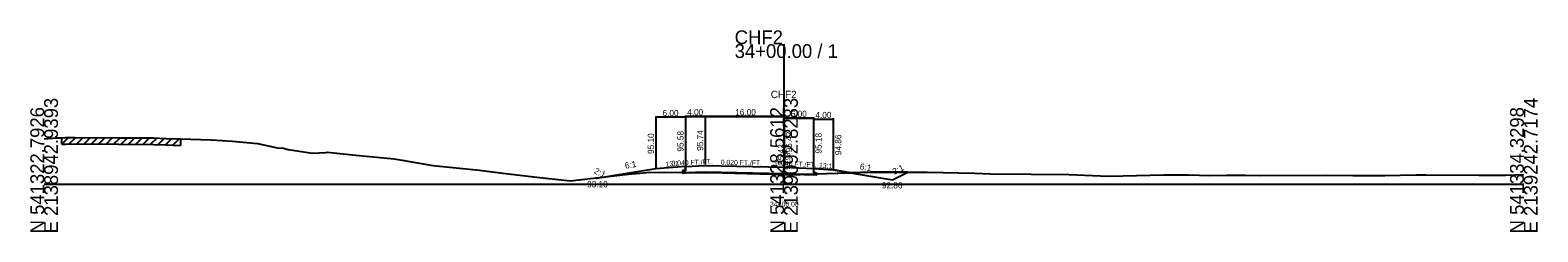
# Model space of a CAD drawing. Extents: x -12831 to 2303, y -10 to 39065.
# Drawn here: x 997.2 to 1302.8, y 7990.3 to 8031.2 of the extents above; entities that cross this region are included whole.
import ezdxf

# ---------------------------------------------------------------- set-up
doc = ezdxf.new("R2010")
doc.units = 0
for name, color, linetype in [('Level 5', 7, 'Continuous'), ('Level 53', 7, 'Continuous'), ('Level 54', 7, 'Continuous'), ('Level 55', 7, 'Continuous'), ('Level 7', 7, 'Continuous'), ('RD_GPK_XS_Cell', 7, 'Continuous'), ('RD_XS_EwShp', 7, 'Continuous'), ('RD_XS_ExGround', 7, 'Continuous'), ('RD_XS_ExPaveRet', 7, 'Continuous'), ('RD_XS_Pave', 7, 'Continuous'), ('RD_XS_TX_Baseline', 7, 'Continuous'), ('RD_XS_TX_Ditch', 7, 'Continuous'), ('RD_XS_TX_Elev_EX', 7, 'Continuous'), ('RD_XS_TX_Elev_PR', 7, 'Continuous'), ('RD_XS_TX_Station', 7, 'Continuous')]:
    doc.layers.add(name, color=color, linetype=linetype)

msp = doc.modelspace()

# ---------------------------------------------------------------- linework, layer by layer
at = {"layer": 'Level 5'}
for p, q in [((1130, 8002.75), (1129.5, 8002.73)), ((1130, 8003.58), (1130, 8002.75)), ((1156, 8003.18), (1156, 8002.35)), ((1129.5, 8002.73), (1129.5, 8002.23)), ((1129.5, 8002.23), (1130, 8002.25)), ((1134, 8002.41), (1130, 8002.25)), ((1134, 8002.41), (1130, 8002.25)), ((1130, 8002.25), (1134, 8002.41)), ((1150, 8002.09), (1134, 8002.41)), ((1150, 8002.09), (1134, 8002.41)), ((1134, 8002.41), (1150, 8002.09)), ((1134, 8002.41), (1150, 8002.09)), ((1156, 8001.85), (1150, 8002.09)), ((1150, 8002.09), (1156, 8001.85)), ((1150, 8002.09), (1156, 8001.85)), ((1156, 8002.35), (1156.5, 8002.33)), ((1156.5, 8001.83), (1156, 8001.85)), ((1156.5, 8002.33), (1156.5, 8001.83))]:
    msp.add_line(p, q, dxfattribs=at)
at = {"layer": 'Level 54'}
for p, q in [((1124, 8013.73), (1124, 8003.3)), ((1130, 8013.53), (1124, 8013.53)), ((1130, 8013.89), (1130, 8003.78)), ((1130, 8013.89), (1130, 8003.78)), ((1130, 8013.89), (1130, 8003.78)), ((1130, 8013.73), (1130, 8003.78)), ((1130, 8013.69), (1134, 8013.69)), ((1130, 8013.69), (1134, 8013.69)), ((1134, 8013.69), (1130, 8013.69)), ((1134, 8013.89), (1134, 8003.94)), ((1134, 8013.89), (1134, 8003.94)), ((1134, 8013.89), (1134, 8003.94)), ((1134, 8013.89), (1134, 8003.94)), ((1134, 8013.89), (1134, 8003.94)), ((1134, 8013.89), (1134, 8003.94)), ((1134, 8013.89), (1134, 8003.94)), ((1134, 8013.69), (1150, 8013.69)), ((1134, 8013.69), (1150, 8013.69)), ((1150, 8013.69), (1134, 8013.69)), ((1150, 8013.69), (1134, 8013.69)), ((1150, 8013.89), (1150, 8003.62)), ((1150, 8013.89), (1150, 8003.62)), ((1150, 8013.89), (1150, 8003.62)), ((1150, 8013.89), (1150, 8003.62)), ((1150, 8013.57), (1150, 8003.62)), ((1150, 8013.57), (1150, 8003.62)), ((1150, 8013.57), (1150, 8003.62)), ((1150, 8013.37), (1156, 8013.37)), ((1156, 8013.37), (1150, 8013.37)), ((1156, 8013.37), (1150, 8013.37)), ((1156, 8013.57), (1156, 8003.38)), ((1156, 8013.57), (1156, 8003.38)), ((1156, 8013.57), (1156, 8003.38)), ((1156, 8013.33), (1156, 8003.38)), ((1156, 8013.13), (1160, 8013.13)), ((1160, 8013.33), (1160, 8003.06))]:
    msp.add_line(p, q, dxfattribs=at)
at = {"layer": 'Level 7'}
for p, q in [((1124, 8003.1), (1112, 8001.1)), ((1130, 8003.58), (1124, 8003.1)), ((1156, 8003.18), (1160, 8002.86)), ((1160, 8002.86), (1172, 8000.86)), ((1112, 8001.1), (1111.76, 8001.22)), ((1172, 8000.86), (1175.11, 8002.42))]:
    msp.add_line(p, q, dxfattribs=at)
at = {"layer": 'RD_GPK_XS_Cell'}
for p, q in [((1150, 8000), (1150, 8028.36)), ((1000, 8000), (1150, 8000)), ((1150, 8000), (1300, 8000))]:
    msp.add_line(p, q, dxfattribs=at)
at = {"layer": 'RD_XS_EwShp'}
for points in [[(1130, 8003.58), (1124, 8003.1), (1114.88, 8001.58), (1118.49, 8001.99), (1121.48, 8002.27), (1122.75, 8002.38), (1129.5, 8002.35), (1129.5, 8002.73), (1130, 8002.75)], [(1156.5, 8002.33), (1156.5, 8002.06), (1163.05, 8002.27), (1163.47, 8002.28), (1160, 8002.86), (1156, 8003.18), (1156, 8002.35)], [(1111.76, 8001.22), (1114.88, 8001.58), (1112, 8001.1)], [(1129.5, 8002.35), (1132.24, 8002.34), (1130, 8002.25), (1129.5, 8002.23)], [(1153.25, 8001.96), (1150, 8002.09), (1134, 8002.41), (1132.24, 8002.34), (1135.7, 8002.32), (1137.56, 8002.27), (1150.09, 8001.92), (1150.91, 8001.9), (1151.63, 8001.91)], [(1156, 8001.85), (1153.25, 8001.96), (1156.5, 8002.06), (1156.5, 8001.83)], [(1163.47, 8002.28), (1172, 8000.86), (1175.11, 8002.42), (1167.53, 8002.4)]]:
    msp.add_lwpolyline(points, close=True, dxfattribs=at)
at = {"layer": 'RD_XS_ExGround'}
for p, q in [((1000, 8009.2), (1002.47, 8009.38)), ((1002.47, 8009.38), (1003.59, 8009.39)), ((1003.59, 8009.39), (1004.33, 8009.41)), ((1004.33, 8009.41), (1006.27, 8009.45)), ((1006.27, 8009.45), (1015.13, 8009.4)), ((1015.13, 8009.4), (1022.16, 8009.35)), ((1022.16, 8009.35), (1024.68, 8009.25)), ((1024.68, 8009.25), (1027.66, 8009.14)), ((1027.66, 8009.14), (1033.85, 8008.97)), ((1033.85, 8008.97), (1036.12, 8008.82)), ((1036.12, 8008.82), (1038.16, 8008.69)), ((1038.16, 8008.69), (1043.26, 8008.22)), ((1043.26, 8008.22), (1046.72, 8007.46)), ((1046.72, 8007.46), (1047.56, 8007.28)), ((1047.56, 8007.28), (1048.28, 8007.36)), ((1048.28, 8007.36), (1049.5, 8007.01)), ((1049.5, 8007.01), (1054.41, 8006.29)), ((1054.41, 8006.29), (1057.13, 8006.43)), ((1057.13, 8006.43), (1057.44, 8006.44)), ((1057.44, 8006.44), (1058.03, 8006.37)), ((1058.03, 8006.37), (1063.84, 8005.81)), ((1063.84, 8005.81), (1070.97, 8005.1)), ((1070.97, 8005.1), (1072.58, 8004.86)), ((1072.58, 8004.86), (1078.78, 8003.76)), ((1078.78, 8003.76), (1088.24, 8002.79)), ((1088.24, 8002.79), (1092.97, 8002.23)), ((1092.97, 8002.23), (1099.31, 8001.48)), ((1099.31, 8001.48), (1106.62, 8000.63)), ((1106.62, 8000.63), (1118.49, 8001.99)), ((1118.49, 8001.99), (1121.48, 8002.27)), ((1121.48, 8002.27), (1122.75, 8002.38)), ((1122.75, 8002.38), (1135.7, 8002.32)), ((1135.7, 8002.32), (1137.56, 8002.27)), ((1137.56, 8002.27), (1150.09, 8001.92)), ((1150.09, 8001.92), (1150.91, 8001.9)), ((1150.91, 8001.9), (1151.63, 8001.91)), ((1151.63, 8001.91), (1163.05, 8002.27)), ((1163.05, 8002.27), (1167.53, 8002.4)), ((1167.53, 8002.4), (1175.83, 8002.42)), ((1175.83, 8002.42), (1179.08, 8002.39)), ((1179.08, 8002.39), (1188.61, 8002.2)), ((1188.61, 8002.2), (1191.88, 8002.06)), ((1191.88, 8002.06), (1200.05, 8002)), ((1200.05, 8002), (1207.76, 8001.91)), ((1207.76, 8001.91), (1214.18, 8001.68)), ((1214.18, 8001.68), (1215.96, 8001.62)), ((1215.96, 8001.62), (1226.96, 8001.84)), ((1226.96, 8001.84), (1232.05, 8001.9)), ((1232.05, 8001.9), (1236.31, 8001.75)), ((1236.31, 8001.75), (1239.75, 8001.77)), ((1239.75, 8001.77), (1243.49, 8001.81)), ((1243.49, 8001.81), (1246.68, 8001.74)), ((1246.68, 8001.74), (1259.96, 8001.8)), ((1259.96, 8001.8), (1265.31, 8001.74)), ((1265.31, 8001.74), (1271.84, 8001.72)), ((1271.84, 8001.72), (1278.1, 8001.87)), ((1278.1, 8001.87), (1280.13, 8001.85)), ((1280.13, 8001.85), (1290.88, 8001.78)), ((1290.88, 8001.78), (1296.27, 8001.82)), ((1296.27, 8001.82), (1300, 8001.96))]:
    msp.add_line(p, q, dxfattribs=at)
at = {"layer": 'RD_XS_ExPaveRet'}
for p, q in [((1003.59, 8008.09), (1004.92, 8009.42)), ((1003.59, 8008.09), (1003.59, 8009.39)), ((1005.09, 8008.13), (1006.42, 8009.45)), ((1006.59, 8008.15), (1007.88, 8009.45)), ((1008.09, 8008.14), (1009.38, 8009.44)), ((1009.59, 8008.14), (1010.88, 8009.43)), ((1011.09, 8008.13), (1012.38, 8009.42)), ((1012.59, 8008.12), (1013.88, 8009.41)), ((1014.09, 8008.11), (1015.38, 8009.4)), ((1015.59, 8008.1), (1016.88, 8009.39)), ((1017.09, 8008.09), (1018.38, 8009.38)), ((1018.59, 8008.08), (1019.88, 8009.37)), ((1020.09, 8008.07), (1021.38, 8009.36)), ((1021.59, 8008.06), (1022.86, 8009.32)), ((1023.09, 8008.01), (1024.34, 8009.26)), ((1024.59, 8007.95), (1025.85, 8009.21)), ((1026.09, 8007.9), (1027.35, 8009.15)), ((1027.66, 8009.14), (1027.66, 8007.84)), ((1003.59, 8008.09), (1004.33, 8008.11)), ((1004.33, 8008.11), (1006.27, 8008.15)), ((1006.27, 8008.15), (1015.13, 8008.1)), ((1015.13, 8008.1), (1022.16, 8008.05)), ((1022.16, 8008.05), (1024.68, 8007.95)), ((1024.68, 8007.95), (1027.66, 8007.84))]:
    msp.add_line(p, q, dxfattribs=at)
at = {"layer": 'RD_XS_Pave'}
for p, q in [((1130, 8003.58), (1134, 8003.74)), ((1134, 8003.74), (1150, 8003.42)), ((1150, 8003.42), (1156, 8003.18))]:
    msp.add_line(p, q, dxfattribs=at)

# ---------------------------------------------------------------- texts
at = {"layer": 'Level 53'}
for s, rotation, p in [('95.10', 90, (1123.63, 8006.1)), ('95.58', 90, (1129.63, 8006.58)), ('95.74', 90, (1133.62, 8006.74)), ('95.74', 90, (1133.62, 8006.74)), ('95.42', 90, (1151.63, 8006.42)), ('95.42', 90, (1151.63, 8006.42)), ('95.18', 90, (1157.63, 8006.18)), ('94.86', 90, (1161.63, 8005.86)), ('6:1', 9.4623, (1117.84, 8003.09)), ('6:1', 350.5377, (1165.3, 8002.99))]:
    msp.add_text(s, height=1.25, rotation=rotation, dxfattribs=at).set_placement(p)
msp.add_text('92.86', height=1.25, dxfattribs=at).set_placement((1169.83, 7999.11))
at = {"layer": 'Level 54'}
for s, p in [('6.00', (1125.37, 8013.78)), ('4.00', (1130.37, 8013.94)), ('4.00', (1130.37, 8013.94)), ('4.00', (1130.37, 8013.94)), ('16.00', (1140.12, 8013.94)), ('16.00', (1140.12, 8013.94)), ('16.00', (1140.12, 8013.94)), ('16.00', (1140.12, 8013.94)), ('6.00', (1151.37, 8013.62)), ('6.00', (1151.37, 8013.62)), ('6.00', (1151.37, 8013.62)), ('4.00', (1156.37, 8013.38))]:
    msp.add_text(s, height=1.25, dxfattribs=at).set_placement(p)
at = {"layer": 'Level 55'}
for s, height, rotation, p in [('2:1', 1.25, 333.4349, (1111.37, 8002.25)), ('13:1', 1, 4.5739, (1126.03, 8003.51)), ('0.040 FT./FT.', 1, 2.2906, (1127.22, 8003.72)), ('0.040 FT./FT.', 1, 2.2906, (1127.22, 8003.72)), ('0.040 FT./FT.', 1, 2.2906, (1127.22, 8003.72)), ('0.020 FT./FT.', 1, 358.8542, (1137.18, 8003.93)), ('0.020 FT./FT.', 1, 358.8542, (1137.18, 8003.93)), ('0.020 FT./FT.', 1, 358.8542, (1137.18, 8003.93)), ('0.020 FT./FT.', 1, 358.8542, (1137.18, 8003.93)), ('0.040 FT./FT.', 1, 357.7094, (1148.24, 8003.74)), ('0.040 FT./FT.', 1, 357.7094, (1148.24, 8003.74)), ('0.040 FT./FT.', 1, 357.7094, (1148.24, 8003.74)), ('13:1', 1, 355.4261, (1157.07, 8003.35)), ('2:1', 1.25, 26.5651, (1172.38, 8001.89))]:
    msp.add_text(s, height=height, rotation=rotation, dxfattribs=at).set_placement(p)
at = {"layer": 'RD_GPK_XS_Cell'}
for s, p in [('CHF2', (1140, 8028.36)), ('34+00.00 / 1', (1140, 8025.56))]:
    msp.add_text(s, height=2.8, dxfattribs=at).set_placement(p)
for s, p in [('N 541322.7926', (1000, 7990)), ('E 2138942.9393', (1002.8, 7990)), ('N 541328.5612', (1150, 7990)), ('E 2139092.8283', (1152.8, 7990)), ('N 541334.3298', (1300, 7990)), ('E 2139242.7174', (1302.8, 7990))]:
    msp.add_text(s, height=2.8, rotation=90, dxfattribs=at).set_placement(p)
at = {"layer": 'RD_XS_TX_Baseline'}
msp.add_text('CHF2', height=1.5, dxfattribs=at).set_placement((1147.31, 8017.42))
at = {"layer": 'RD_XS_TX_Ditch'}
msp.add_text('93.10', height=1.25, dxfattribs=at).set_placement((1110.08, 7999.35))
at = {"layer": 'RD_XS_TX_Elev_EX'}
msp.add_text('93.93', height=1, rotation=90, dxfattribs=at).set_placement((1151.25, 8002.93))
at = {"layer": 'RD_XS_TX_Elev_PR'}
msp.add_text(' 95.42', height=1.25, rotation=90, dxfattribs=at).set_placement((1150, 8003.42))
at = {"layer": 'RD_XS_TX_Station'}
msp.add_text('34+00.00', height=1, dxfattribs=at).set_placement((1147.17, 7995.42))

doc.saveas('drawing.dxf')
